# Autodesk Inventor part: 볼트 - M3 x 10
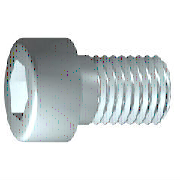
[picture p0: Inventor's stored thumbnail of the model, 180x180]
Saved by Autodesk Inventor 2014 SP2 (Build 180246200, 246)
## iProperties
Created: 2012-02
Part Number: 볼트 - M3 x 10
Material: 스테인리스강
Description: 6각 소켓 머리 캡 나사
Document SubType Name: Modeling
Standard: ISO 4762
Designer: mduedu
Standard Revision: Fourth edition 2004-03-01
Standards Organization: ISO
Language: ko-KR
Size Designation: M3 x 10
Categories: <MemberInstance><Categories><Category DisplayName="조임쇠" InternalName="e4da775c-781d-43d5-af7c-5136215cf5a6" Mnemonic="FSTN"><Category DisplayName="볼트" InternalN
Density: 8.08 g/cm^3
Mass: 1.0701 g
Surface Area: 2.01851 cm^2
Volume: 0.132438 cm^3
Appearance: 반광택
IsCustomPart: 0
Author: mduedu
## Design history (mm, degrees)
sketch "스케치1"
  geometry: L1 (-0.867, 0)-(10, 0); L2 (10, 0)-(10, 1.5); L3 (10, 1.5)-(1.25, 1.5); L4 (1.25, 1.5)-(0.943, 1.5); L5 (0.943, 1.5)-(0, 1.5); L6 (0, 1.5)-(0, 2.75); L7 (0, 2.75)-(-3, 2.75); L8 (-3, 2.75)-(-3, 1.443); L9 (-3, 1.443)-(-1.7, 1.443); L10 (-1.7, 1.443)-(-0.867, 0); L11 (-5.6, 0)-(12.6, 0) reference; L12 (0, -0.55)-(0, 3.3) reference; L13 (1.25, 1.5)-(0, 1.5)
  constraints: 22 end point, 6 parallel, 2 collinear, 2 perpendicular, 1 horizontal, 1 point on line
  dimensions: "d1" = 8.75 distance from line of L3.end L2 (= GEL); "d2" = 0.30683 distance of L4.end L3.end (computed from GAL); "d3" = 3 distance between parallel lines of L8 L6 (= KOH); "d4" = 1.3 distance of L8.end L9.end (= INTI); "d5" = 60 deg angle of L10 L1; "d6" = 3 diameter of L3 L1 (= GD); "d7" = 3 diameter of L5 L1 (= BDM); "d8" = 2.88675 diameter of L9 L1 (= 1.1547 x SW); "d9" = 5.5 diameter of L7 L1 (= KOD); "d26" = 10 distance between parallel lines of L12 L2 (= NLG)
revolve "본체" sketch "스케치1" stored, may be unused: angle "d10" = 90 deg
sketch "스케치2"
  geometry: L1 (0, -3.85)-(0, 3.85) reference; L2 (-3.85, 0)-(3.85, 0) reference; L3 (1.443, 0)-(0.722, -1.25); L4 (0.722, -1.25)-(-0.722, -1.25); L5 (-0.722, -1.25)-(-1.443, 0); L6 (-1.443, 0)-(-0.722, 1.25); L7 (-0.722, 1.25)-(0.722, 1.25); L8 (0.722, 1.25)-(1.443, 0); 2 further points
  constraints: 12 end point, 1 coincident, 1 horizontal alignment, 1 point on line, 12 other
extrude "슬롯" join sketch "스케치2" stored distance "d11" = 10; taper "d12" = 0 deg
workplane "Work Plane1"
fillet "Fillet2" dims "d30" = 0.1 (= R)
body "Solid1"
fillet "모깎기1" dims "d17" = 0.3 (= RR)
feature "스레드" dims "d13" = 8.75 (= GEL), "d14" = 0
chamfer "모따기1" distance "d15" = 0.30673 (= -0.5 x SPD + 0.5 x GD); stored, may be unused: second distance "d16" = 0.30673 (= GUL), angle "d27" = 45 deg
other parameters: "GD" = 3 [user parameter; used in 2 equation terms], "NLG" = 10 [user parameter; used in 1 equation term], "GEL" = 8.75 [user parameter; used in 2 equation terms], "KOD" = 5.5 [user parameter; used in 1 equation term], "KOH" = 3 [user parameter; used in 1 equation term], "INTI" = 1.3 [user parameter; used in 1 equation term], "GAL" = 0.30673 (= 0.61345 x PTC) [user parameter; used in 1 equation term], "GUL" = 0.30673 (= 0.61345 x PTC) [user parameter; used in 1 equation term], "BDM" = 3 (= NND) [user parameter; used in 1 equation term], "SW" = 2.5 [user parameter; used in 2 equation terms], "RR" = 0.3 [user parameter; used in 1 equation term], "SPD" = 2.38655 (= NND - 1.2269 x PTC) [user parameter; used in 1 equation term], "d19" = 0, "d28" = 0, "d29" = 0, "R" = 0.1 [user parameter; used in 1 equation term], "TOA" = 30 deg [user parameter], "GD1" = 2.38655 (= THREADDIA - 1.2269 x PTC) [user parameter], "THREADDIA" = 3 [user parameter; used in 1 equation term], "FAWI" = 45 deg [user parameter], "PTC" = 0.5 [user parameter; used in 5 equation terms], "NND" = 3 [user parameter; used in 2 equation terms], "E0" = 2.8875 (= 1.155 x SW) [user parameter]
